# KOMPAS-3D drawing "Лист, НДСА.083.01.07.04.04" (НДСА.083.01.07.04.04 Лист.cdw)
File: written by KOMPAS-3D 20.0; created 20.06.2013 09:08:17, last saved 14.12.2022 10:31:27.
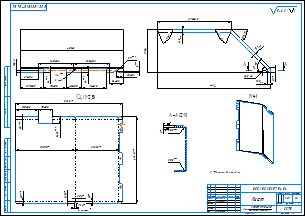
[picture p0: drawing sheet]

Sheet 1: A2, landscape

Document properties: Автор: Шубников; Знак неуказанной шероховатости: 4; Параметр неуказанной шероховатости: Ra6.3; Полное имя файла: НДСА.083.01.07.04.04 Лист.m3d; PLM_CDWXDTO: <item xmlns="http://appius.ru/pdm" xmlns:xs="http://www.w3.org/2001/XMLSchema" xmlns:xsi="http://www.w3.org/2001/XMLSchema-instance" xsi:type="item">  <element xmlns:d2p1="http://v8.1c.ru/8.1/data/enterprise/current-config" xsi:type="d2p1:CatalogRef.aps_Элемен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; Масса: 1.68856; PDM_DOCXDTO: <item xmlns="http://appius.ru/pdm" xmlns:xs="http://www.w3.org/2001/XMLSchema" xmlns:xsi="http://www.w3.org/2001/XMLSchema-instance" xsi:type="item">  <element xmlns:d2p1="http://v8.1c.ru/8.1/data/enterprise/current-config" xsi:type="d2p1:CatalogRef.aps_Элемен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; PDM_ITEMXDTO: <item xmlns="http://appius.ru/pdm" xmlns:xs="http://www.w3.org/2001/XMLSchema" xmlns:xsi="http://www.w3.org/2001/XMLSchema-instance" xsi:type="item">  <element xmlns:d2p1="http://v8.1c.ru/8.1/data/enterprise/current-config" xsi:type="d2p1:CatalogRef.aps_Элемен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; PDM_DRAWINGXDTO: <item xmlns="http://appius.ru/pdm" xmlns:xs="http://www.w3.org/2001/XMLSchema" xmlns:xsi="http://www.w3.org/2001/XMLSchema-instance" xsi:type="item">  <element xmlns:d2p1="http://v8.1c.ru/8.1/data/enterprise/current-config" xsi:type="d2p1:CatalogRef.aps_Элемен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; Организация: ЭСТО-Вакуум

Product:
- Part/product: Лист  | designation НДСА.083.01.07.04.04
    Материал: Лист$d1 ГОСТ 19904-90;10 ГОСТ 16523-97$ (density 7856 kg/m3)
    Масса: 1.68856
    additional columns: <item xmlns="http://appius.ru/pdm" xmlns:xs="http://www.w3.org/2001/XMLSchema" x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; <item xmlns="http://appius.ru/pdm" xmlns:xs="http://www.w3.org/2001/XMLSchema" x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; <item xmlns="http://appius.ru/pdm" xmlns:xs="http://www.w3.org/2001/XMLSchema" x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
    source file: НДСА.083.01.07.04.04 Лист.cdw

Title block, sheet 1: Наименование: Лист; designation: НДСА.083.01.07.04.04; Материал: Лист 1 ГОСТ 19904-90 10 ГОСТ 16523-97; Масса: 1,69; scale: 1:2; Количество листов документа: 1; organisation: ЭСТО; Форматы листов документа: A2; stored path: C:\Пищагина\Чертежи Ялика\УКРД.839.01.06.04.04 - Лист.cdw; Разработал: Щербакова; Проверил: Горностаев; Утвердил: Белецкий; Разработал, date: 14.12.2022

Views: Проекционный вид 2, Вид 4, Развертка, Разрез А-А
Referenced files in C:\Users\cherbakova\Desktop\Виноград\Новая папка (4)\: НДСА.083.01.07.04.04 Лист.m3d
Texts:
  Гл 1
  Пользовательская
  Ra6.3
  Ra6.3 ( )
  НДСА.083.01.07.04.04 Лист
Dimensions and other numbers on the sheet: 403±1; 89,5±0,5; 90±0,5; 60±0,5; 96±0,5; 28±0,2; 54±0,2; 5; 7; 69±0,2; 140±0,2; 9±0,2; 16; 4; 3 отв.; 170; 11,5; 290±0,5; 19; 441; 22,5; 10,7*; 290,12; 212,36; 521,6; 10,7; 1,06; 11,34; 9,34; 4 места; 10; 422,67; 110±0,5; 70±0,5; 34,13; 1:2; 1; 1,69; 14.12.2022

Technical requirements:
  *Размеры для справок.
